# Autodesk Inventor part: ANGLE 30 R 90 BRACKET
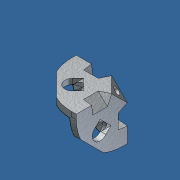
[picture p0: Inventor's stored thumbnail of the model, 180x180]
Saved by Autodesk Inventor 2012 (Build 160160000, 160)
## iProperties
Created: 2012-08
Part Number: ANGLE 30 R 90 BRACKET
Document SubType Name: Modeling
Designer: Administrator
Density: 2.71 g/cm^3
Material: Aluminum-6061
Mass: 12.811 g
Surface Area: 34.7076 cm^2
Volume: 4.72731 cm^3
Author: Administrator
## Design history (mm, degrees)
feature "Base1"
body "Solid1"
